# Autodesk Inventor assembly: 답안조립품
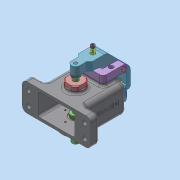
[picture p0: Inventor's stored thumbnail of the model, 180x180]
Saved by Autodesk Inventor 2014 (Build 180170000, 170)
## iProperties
Created: 2023-12
Part Number: 답안조립품
Document SubType Name: Assembly
Designer: dg
Author: dg
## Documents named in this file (14)
- C:\Users\dg\Desktop\731208V1008\답안조립품.iam
- C:\Users\dg\Desktop\731208V1008\본체.ipt
- C:\Users\dg\Desktop\731208V1008\가이드 부시.ipt
- C:\Users\dg\Desktop\731208V1008\조절 부시.ipt
- C:\Users\dg\Desktop\731208V1008\클램프 샤프트.ipt
- C:\Users\dg\Desktop\731208V1008\가공품.ipt
- C:\Users\dg\Desktop\731208V1008\고정대.ipt
- C:\Users\dg\Desktop\731208V1008\육각 머리 볼트 M6 x 12.ipt
- C:\Users\dg\Desktop\731208V1008\클램프.ipt
- C:\Users\dg\Desktop\731208V1008\스프링.ipt
- C:\Users\dg\Desktop\731208V1008\육각 소켓 머리 볼트 M3 x 30.ipt
- C:\Users\dg\Desktop\731208V1008\핀.ipt
- C:\Users\dg\Desktop\731208V1008\브라켓.ipt
- C:\Users\dg\Desktop\731208V1008\육각 소켓 머리 볼트 M3 x 8.ipt
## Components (4 placed, 4 different names)
1. 가이드 부시:1
2. 가공품:1
3. 고정대:1
4. 핀:1
